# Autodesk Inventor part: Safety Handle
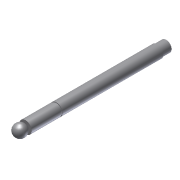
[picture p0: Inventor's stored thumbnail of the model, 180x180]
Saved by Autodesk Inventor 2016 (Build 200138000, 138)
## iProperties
Shininess: 77.0
Length Units: 11269
Angle Units: 11279
Time Units: 11290
Mass Units: 11283
Length Display Precision: 3
Angle Display Precision: 2
Created: 2002-02
Part Number: Safety Handle
Document SubType Name: Modeling
Designer: ***
Density: 1 g/cm^3
Material: Generic
Mass: 54.3914 g
Surface Area: 130.219 cm^2
Volume: 54.3914 cm^3
Appearance: Default
Density: 0.0
Volumn: 0.0
Area: 0.0
PropertySet Name: Model Information
Control State: 0
Master: False
Checked Out: False
Author: ***
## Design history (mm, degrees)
sketch "Sketch1"
  geometry: L1 (0, 205)-(8, 205); L2 (8, 205)-(8, 192); L3 (8, 192)-(9, 192); L4 (9, 192)-(9, 45); L5 (9, 45)-(8, 45); L6 (8, 45)-(8, 43); L7 (8, 43)-(9, 43); L8 (9, 43)-(9, 0); L9 (9, 0)-(0, 0); L10 (0, 0)-(0, 205)
  constraints: 20 end point, 7 parallel, 1 collinear, 1 horizontal, 1 perpendicular
  dimensions: "d0" = 13 distance of L1.end L2.end; "d1" = 2 distance of L4.end L7.end; "d2" = 43 distance of L7.end L8.end; "d3" = 205 distance of L9.end L1.start; "d4" = 16 diameter of L2 L10; "d5" = 18 diameter of L4 L10; "d6" = 16 diameter of L6.end L10
revolve "Revolution1" sketch "Sketch1" stored, may be unused: angle "d7" = 90 deg
sketch "Sketch2"
  geometry: L1 (0, 1)-(0, -17); L2 (-9, 0)-(9, 0) reference; A1 r 9 centre (0, -8) between (0, -17) and (0, 1)
  constraints: 2 end point, 2 point on circle, 1 centre point, 1 midpoint, 1 vertical
  dimensions: "d8" = 9 radius of A1; "d9" = 1 distance from line of L2 L1.start
revolve "Revolution2" sketch "Sketch2" stored, may be unused: angle "d10" = 90 deg
body "Solid1"
